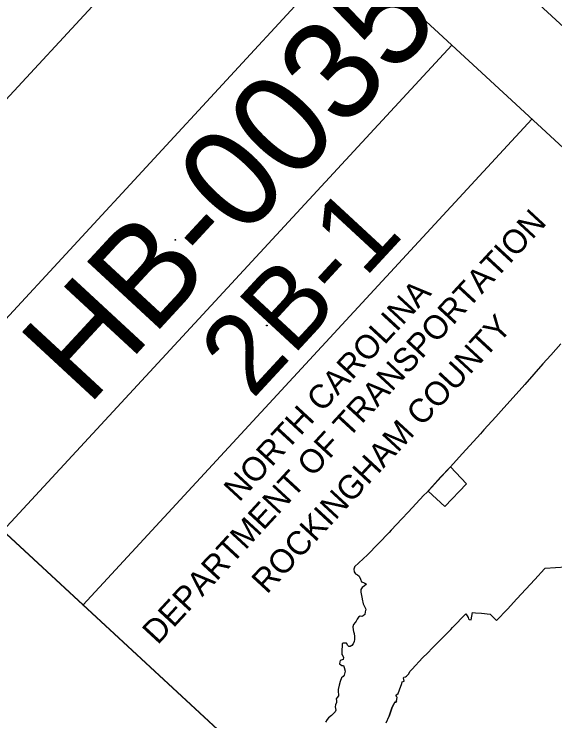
# Model space of a CAD drawing. Extents: x 1768274 to 1769121, y 999922 to 1000687.
# Drawn here: x 1768951.2 to 1768967.56, y 1000292.6 to 1000313.97 of the extents above; entities that cross this region are included whole.
import ezdxf

# ---------------------------------------------------------------- set-up
doc = ezdxf.new("R2010")
doc.units = 0
for name, color, linetype in [('E_NCDOT_Terrain_Model_Contour_Imported', 7, 'Continuous'), ('E_NCDOT_Terrain_Model_Contour_Major', 7, 'Continuous'), ('E_NCDOT_Terrain_Model_Flow_Arrows', 7, 'Continuous'), ('E_NCDOT_Terrain_Model_Points_High', 7, 'Continuous'), ('E_NCDOT_Terrain_Model_Spot_Elevation', 7, 'Continuous'), ('E_NCDOT_Terrain_Model_Triangle_Vertices', 7, 'Continuous')]:
    doc.layers.add(name, color=color, linetype=linetype)

msp = doc.modelspace()

# ---------------------------------------------------------------- linework, layer by layer
at = {"layer": 'E_NCDOT_Terrain_Model_Contour_Imported'}
msp.add_lwpolyline([(1768737.288, 1000073.608), (1768947.711, 1000301.251), (1769102.655, 1000158.029), (1768892.232, 999930.385)], close=True, dxfattribs=at)
at = {"layer": 'E_NCDOT_Terrain_Model_Contour_Major'}
for p, q in [((1768961.29, 1000315.942), (1768737.288, 1000073.608)), ((1769116.231, 1000172.715), (1768961.29, 1000315.942)), ((1768964.436, 1000313.034), (1768950.86, 1000298.347)), ((1768966.859, 1000310.794), (1768953.284, 1000296.107)), ((1769102.655, 1000158.029), (1768947.714, 1000301.255))]:
    msp.add_line(p, q, dxfattribs=at)
for centre in [(1768956.075, 1000307.144), (1768958.843, 1000304.553), (1768953.284, 1000296.107), (1768953.284, 1000296.107), (1768953.284, 1000296.107)]:
    msp.add_circle(centre, 0.012, dxfattribs=at)
at = {"layer": 'E_NCDOT_Terrain_Model_Flow_Arrows'}
for points in [[(1768967.736, 1000304.002), (1768967.435, 1000303.655), (1768967.197, 1000303.396), (1768966.647, 1000302.773), (1768966.478, 1000302.579), (1768966.288, 1000302.363), (1768965.935, 1000301.973), (1768965.769, 1000301.789), (1768965.407, 1000301.396), (1768965.307, 1000301.272), (1768964.874, 1000300.8), (1768964.751, 1000300.675), (1768964.4, 1000300.279), (1768964.1, 1000299.962), (1768963.687, 1000299.506), (1768963.597, 1000299.419), (1768963.124, 1000298.911), (1768962.925, 1000298.703), (1768962.609, 1000298.368), (1768962.542, 1000298.292), (1768961.887, 1000297.622), (1768961.494, 1000297.25), (1768961.495, 1000297.24), (1768961.472, 1000297.181), (1768961.489, 1000297.1), (1768961.526, 1000297.042), (1768961.585, 1000297.009), (1768961.64, 1000296.973), (1768961.677, 1000296.877), (1768961.704, 1000296.8), (1768961.768, 1000296.779), (1768961.811, 1000296.762), (1768961.859, 1000296.734), (1768961.799, 1000296.677), (1768961.726, 1000296.631), (1768961.691, 1000296.573), (1768961.684, 1000296.486), (1768961.727, 1000296.292), (1768961.728, 1000296.278), (1768961.757, 1000296.139), (1768961.84, 1000295.975), (1768961.822, 1000295.889), (1768961.809, 1000295.818), (1768961.76, 1000295.774), (1768961.72, 1000295.757), (1768961.672, 1000295.763), (1768961.615, 1000295.733), (1768961.572, 1000295.668), (1768961.551, 1000295.608), (1768961.52, 1000295.568), (1768961.47, 1000295.511), (1768961.45, 1000295.445), (1768961.451, 1000295.346), (1768961.461, 1000295.295), (1768961.489, 1000295.24), (1768961.498, 1000295.148), (1768961.492, 1000295.061), (1768961.489, 1000294.992), (1768961.454, 1000294.923), (1768961.415, 1000294.871), (1768961.366, 1000294.844), (1768961.325, 1000294.845), (1768961.291, 1000294.877), (1768961.249, 1000294.948), (1768961.139, 1000294.947), (1768961.118, 1000294.929), (1768961.108, 1000294.672), (1768961.112, 1000294.607), (1768961.147, 1000294.566), (1768961.162, 1000294.515), (1768961.153, 1000294.457), (1768961.057, 1000294.422), (1768961.053, 1000294.379), (1768961.046, 1000294.32), (1768961.114, 1000294.274), (1768961.162, 1000294.273), (1768961.178, 1000294.215), (1768961.209, 1000294.103), (1768961.203, 1000294.055)], [(1768962.454, 1000292.542), (1768962.542, 1000292.741), (1768962.55, 1000292.773), (1768962.638, 1000293.013), (1768962.692, 1000293.126), (1768962.716, 1000293.161), (1768962.755, 1000293.165), (1768962.769, 1000293.203), (1768962.79, 1000293.308), (1768962.77, 1000293.341), (1768962.75, 1000293.369), (1768962.781, 1000293.395), (1768962.816, 1000293.429), (1768962.855, 1000293.535), (1768962.925, 1000293.722), (1768962.936, 1000293.773), (1768962.994, 1000293.801), (1768962.979, 1000293.894), (1768962.991, 1000293.918), (1768963.04, 1000293.932), (1768963.065, 1000293.953), (1768963.135, 1000294.018), (1768963.166, 1000294.091), (1768963.239, 1000294.165), (1768963.552, 1000294.499), (1768963.713, 1000294.658), (1768963.844, 1000294.795), (1768964.41, 1000295.356), (1768964.461, 1000295.419), (1768964.865, 1000295.832), (1768964.908, 1000295.774), (1768964.936, 1000295.727), (1768964.943, 1000295.684), (1768964.966, 1000295.665), (1768965.027, 1000295.653), (1768965.065, 1000295.878), (1768965.159, 1000295.865), (1768965.334, 1000295.849), (1768965.604, 1000295.821), (1768965.796, 1000295.632), (1768966.12, 1000295.972), (1768966.402, 1000296.286), (1768966.95, 1000296.875), (1768967.24, 1000297.193), (1768967.264, 1000297.215), (1768967.889, 1000297.252)], [(1768961.203, 1000294.055), (1768961.186, 1000293.977), (1768961.154, 1000293.942), (1768961.102, 1000293.898), (1768961.064, 1000293.79), (1768961.031, 1000293.677), (1768960.999, 1000293.55), (1768961.004, 1000293.464), (1768961.01, 1000293.406), (1768961.012, 1000293.358), (1768960.975, 1000293.308), (1768960.945, 1000293.268), (1768960.948, 1000293.21), (1768960.95, 1000293.148), (1768960.922, 1000293.084), (1768960.915, 1000293.025), (1768960.932, 1000292.918), (1768960.914, 1000292.867), (1768960.802, 1000292.763), (1768960.711, 1000292.684), (1768960.667, 1000292.639), (1768960.62, 1000292.555)], [(1768962.769, 1000293.203), (1768962.755, 1000293.165), (1768962.716, 1000293.161), (1768962.692, 1000293.126), (1768962.638, 1000293.013), (1768962.55, 1000292.773), (1768962.542, 1000292.741)]]:
    msp.add_lwpolyline(points, dxfattribs=at)
at = {"layer": 'E_NCDOT_Terrain_Model_Points_High'}
msp.add_lwpolyline([(1768964.882, 1000299.769), (1768964.225, 1000299.075), (1768963.725, 1000299.547), (1768964.115, 1000299.979), (1768964.4, 1000300.279)], close=True, dxfattribs=at)
at = {"layer": 'E_NCDOT_Terrain_Model_Spot_Elevation'}
msp.add_lwpolyline([(1768729.032, 1000071.305), (1768959.819, 1000320.98), (1769121.372, 1000171.648), (1768890.585, 999921.973)], close=True, dxfattribs=at)
at = {"layer": 'E_NCDOT_Terrain_Model_Triangle_Vertices'}
msp.add_line((1769121.372, 1000171.648), (1768959.819, 1000320.98), dxfattribs=at)

# ---------------------------------------------------------------- texts
at = {"layer": 'E_NCDOT_Terrain_Model_Contour_Major'}
for s, height, p in [('HB-0035', 3, (1768953.419, 1000302.079)), ('2B-1', 2.4, (1768958.406, 1000302.294)), ('DEPARTMENT OF TRANSPORTATION', 0.72001, (1768955.541, 1000294.875)), ('NORTH CAROLINA', 0.72001, (1768958.006, 1000299.192)), ('ROCKINGHAM COUNTY', 0.72001, (1768958.847, 1000296.406)), ('ROADWAY DESIGN ', 1.00003, (1768966.91, 1000287.288))]:
    msp.add_text(s, height=height, rotation=47.2512, dxfattribs=at).set_placement(p)

doc.saveas('drawing.dxf')
